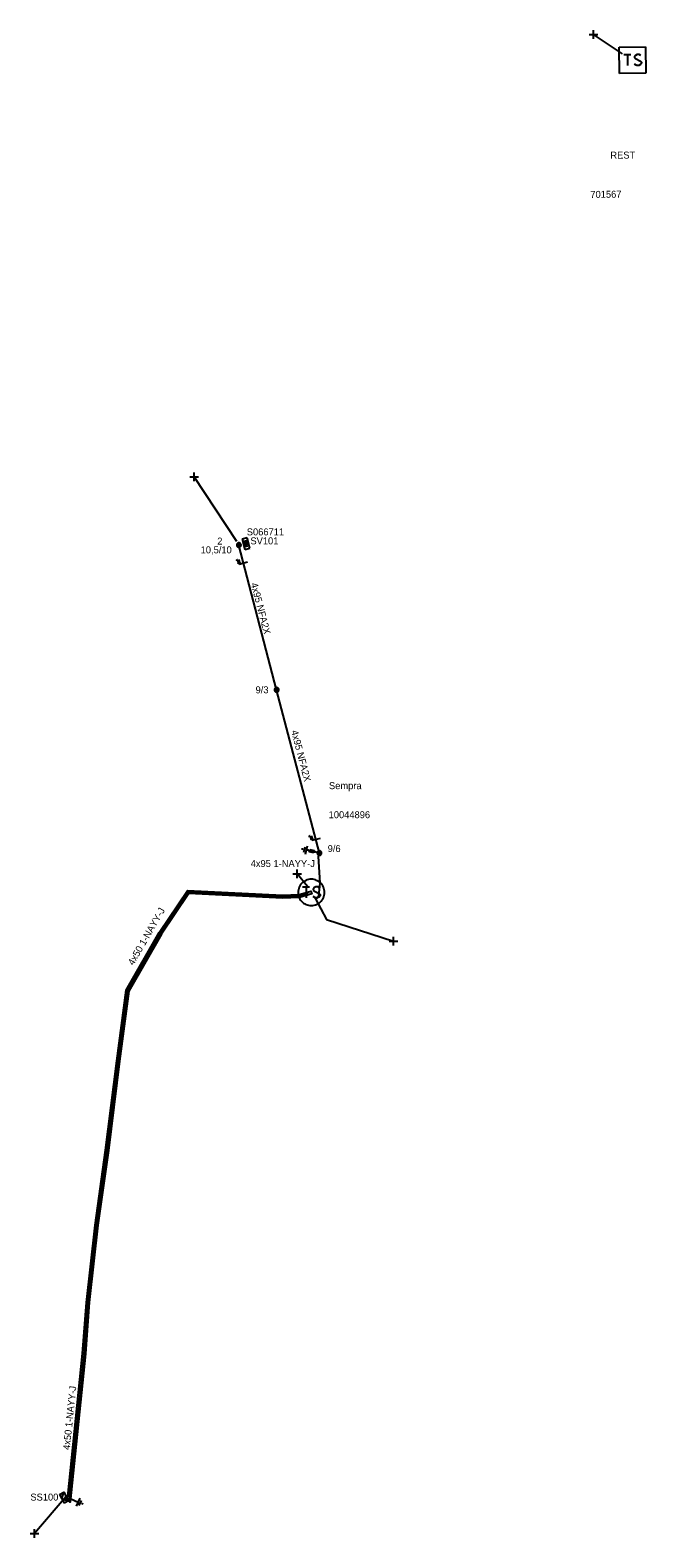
# Model space of a CAD drawing. Extents: x -748492 to -735633, y -1146251 to -1139940.
# Drawn here: x -736938.6 to -736850.2, y -1142511.7 to -1142295.3 of the extents above; entities that cross this region are included whole.
import ezdxf

# ---------------------------------------------------------------- set-up
doc = ezdxf.new("R2010")
doc.units = 0
for name, color, linetype in [('Vrstva 1', 7, 'Continuous'), ('Vrstva 12', 7, 'Continuous'), ('Vrstva 13', 7, 'Continuous'), ('Vrstva 14', 7, 'Continuous'), ('Vrstva 15', 7, 'Continuous'), ('Vrstva 16', 7, 'Continuous'), ('Vrstva 18', 7, 'Continuous'), ('Vrstva 2', 7, 'Continuous'), ('Vrstva 20', 7, 'Continuous'), ('Vrstva 25', 7, 'Continuous'), ('Vrstva 26', 7, 'Continuous'), ('Vrstva 27', 7, 'Continuous'), ('Vrstva 28', 7, 'Continuous'), ('Vrstva 29', 7, 'Continuous'), ('Vrstva 30', 7, 'Continuous'), ('Vrstva 31', 7, 'Continuous'), ('Vrstva 33', 7, 'Continuous'), ('Vrstva 34', 7, 'Continuous'), ('Vrstva 5', 7, 'Continuous'), ('Vrstva 50', 7, 'Continuous'), ('Vrstva 51', 7, 'Continuous'), ('Vrstva 59', 7, 'Continuous'), ('Vrstva 6', 7, 'Continuous'), ('Vrstva 8', 7, 'Continuous'), ('Vrstva 9', 7, 'Continuous')]:
    doc.layers.add(name, color=color, linetype=linetype)

# ---------------------------------------------------------------- blocks, each defined once
blk = doc.blocks.new('NN440')
at = {"layer": 'Vrstva 2'}
for points in [[(0.63, 0), (0.63, 0.06), (0.62, 0.13), (0.6, 0.19), (0.58, 0.25), (0.55, 0.31), (0.51, 0.37), (0.47, 0.42), (0.42, 0.46), (0.37, 0.51), (0.32, 0.54), (0.26, 0.57), (0.2, 0.59), (0.13, 0.61), (0.07, 0.62), (0, 0.63), (-0.06, 0.62), (-0.13, 0.61), (-0.19, 0.59), (-0.26, 0.57), (-0.31, 0.54), (-0.37, 0.51), (-0.42, 0.46), (-0.47, 0.42), (-0.51, 0.37), (-0.54, 0.31), (-0.57, 0.25), (-0.6, 0.19), (-0.62, 0.13), (-0.63, 0.06), (-0.63, 0), (-0.63, -0.07), (-0.62, -0.14), (-0.6, -0.2), (-0.57, -0.26), (-0.54, -0.32), (-0.51, -0.37), (-0.47, -0.43), (-0.42, -0.47), (-0.37, -0.51), (-0.31, -0.55), (-0.26, -0.58), (-0.19, -0.6), (-0.13, -0.62), (-0.06, -0.63), (0, -0.63), (0.07, -0.63), (0.13, -0.62), (0.2, -0.6), (0.26, -0.58), (0.32, -0.55), (0.37, -0.51), (0.42, -0.47), (0.47, -0.43), (0.51, -0.37), (0.55, -0.32), (0.58, -0.26), (0.6, -0.2), (0.62, -0.14), (0.63, -0.07), (0.63, 0)], [(-0.63, 0), (0.63, 0)], [(-0.6, -0.18), (0.57, -0.18)], [(-0.51, -0.32), (0.5, -0.32)], [(-0.37, -0.47), (0.35, -0.47)]]:
    blk.add_lwpolyline(points, dxfattribs=at)
blk = doc.blocks.new('NN840')
at = {"layer": 'Vrstva 15'}
for points in [[(0, 0.62), (0, -0.63)], [(-0.75, -0.71), (-0.75, -0.66)], [(-0.73, -0.76), (-0.75, -0.71)], [(-0.66, -0.8), (-0.73, -0.76)], [(-0.63, -0.8), (-0.66, -0.8)], [(-0.56, -0.76), (-0.63, -0.8)], [(-0.54, -0.71), (-0.56, -0.76)], [(-0.54, -0.38), (-0.54, -0.71)], [(-0.33, -0.38), (-0.33, -0.8)], [(-0.33, -0.64), (-0.13, -0.38)], [(-0.26, -0.56), (-0.09, -0.8)]]:
    blk.add_lwpolyline(points, dxfattribs=at)
blk = doc.blocks.new('NN800')
at = {"layer": 'Vrstva 1'}
for points in [[(-0.44, 0.44), (0.44, -0.44)], [(-0.44, -0.44), (0.44, 0.44)]]:
    blk.add_lwpolyline(points, dxfattribs=at)
blk = doc.blocks.new('NN820')
at = {"layer": 'Vrstva 13'}
for points in [[(0, 0), (0, -1.05)], [(-0.16, -0.81), (0.16, -0.81)], [(-0.16, -1.47), (-0.16, -0.81)], [(0.16, -1.47), (-0.16, -1.47)], [(0, -1.05), (-0.06, -0.93)], [(0, -1.05), (0.06, -0.93)], [(0, -1.47), (0, -1.87)], [(0.16, -0.81), (0.16, -1.47)]]:
    blk.add_lwpolyline(points, dxfattribs=at)
blk = doc.blocks.new('NN620')
at = {"layer": 'Vrstva 8'}
for points in [[(0.75, 0), (-0.75, 0)], [(-0.75, 0), (-0.75, -0.75)], [(0.75, -0.75), (0.75, 0)], [(-0.75, -0.75), (0.75, -0.75)], [(0.37, -0.18), (-0.38, -0.18)], [(-0.38, -0.18), (-0.38, -0.56)], [(-0.38, -0.56), (0.37, -0.56)], [(0.32, -0.23), (-0.33, -0.23)], [(-0.33, -0.23), (-0.33, -0.51)], [(-0.33, -0.51), (0.32, -0.51)], [(0.27, -0.27), (-0.28, -0.27)], [(-0.28, -0.27), (-0.28, -0.46)], [(-0.28, -0.46), (0.27, -0.46)], [(0.23, -0.32), (-0.23, -0.32)], [(-0.23, -0.32), (-0.23, -0.42)], [(-0.23, -0.42), (0.23, -0.42)], [(-0.19, -0.37), (0.19, -0.37)], [(0.23, -0.42), (0.23, -0.32)], [(0.27, -0.46), (0.27, -0.27)], [(0.32, -0.51), (0.32, -0.23)], [(0.37, -0.56), (0.37, -0.18)]]:
    blk.add_lwpolyline(points, dxfattribs=at)
blk = doc.blocks.new('NN630')
at = {"layer": 'Vrstva 9'}
for points in [[(0, -0.7), (-0.7, 0)], [(-0.7, -0.7), (-0.7, 0), (0.7, 0), (0.7, -0.7)], [(-0.7, -0.7), (0.7, -0.7)], [(0, -0.7), (0.7, 0)]]:
    blk.add_lwpolyline(points, dxfattribs=at)
blk = doc.blocks.new('NN810')
at = {"layer": 'Vrstva 14'}
for points in [[(0.63, -1.89), (-0.62, -1.89)], [(0, -0.64), (0, -1.89)], [(0.39, -2.2), (-0.4, -2.2)], [(0, -2.52), (-0.12, -2.52)], [(0.14, -2.52), (0, -2.52)]]:
    blk.add_lwpolyline(points, dxfattribs=at)
blk = doc.blocks.new('NN640')
at = {"layer": 'Vrstva 6'}
for points in [[(-1.89, 1.89), (1.89, 1.89)], [(-1.89, -1.89), (-1.89, 1.89)], [(-1.26, 0.79), (-0.22, 0.79)], [(-0.73, 0.79), (-0.73, -0.79)], [(1.2, 0.66), (0.94, 0.79), (0.66, 0.79), (0.41, 0.66), (0.28, 0.47), (0.28, 0.41), (0.41, 0.22), (1.13, -0.16), (1.26, -0.32), (1.26, -0.47), (1.13, -0.66), (0.91, -0.79), (0.63, -0.79), (0.5, -0.73), (0.28, -0.6)], [(1.89, 1.89), (1.89, -1.89)], [(1.89, -1.89), (-1.89, -1.89)]]:
    blk.add_lwpolyline(points, dxfattribs=at)
blk = doc.blocks.new('NN610')
at = {"layer": 'Vrstva 6'}
for points in [[(1.88, 0), (1.87, 0.2), (1.84, 0.39), (1.79, 0.58), (1.72, 0.77), (1.63, 0.94), (1.52, 1.11), (1.4, 1.26), (1.26, 1.4), (1.1, 1.53), (0.94, 1.63), (0.76, 1.72), (0.58, 1.8), (0.19, 1.88), (0.19, 1.88), (-0.01, 1.89), (-0.21, 1.88), (-0.4, 1.85), (-0.59, 1.8), (-0.78, 1.72), (-0.95, 1.63), (-1.12, 1.53), (-1.27, 1.4), (-1.41, 1.26), (-1.54, 1.11), (-1.64, 0.94), (-1.73, 0.77), (-1.8, 0.58), (-1.86, 0.39), (-1.89, 0.2), (-1.9, 0), (-1.89, -0.2), (-1.86, -0.39), (-1.8, -0.58), (-1.73, -0.77), (-1.64, -0.95), (-1.54, -1.11), (-1.41, -1.27), (-1.27, -1.41), (-1.12, -1.53), (-0.95, -1.64), (-0.78, -1.73), (-0.59, -1.8), (-0.4, -1.85), (-0.21, -1.88), (-0.01, -1.89), (0.19, -1.88), (0.39, -1.85), (0.58, -1.8), (0.76, -1.73), (0.94, -1.64), (1.1, -1.53), (1.26, -1.41), (1.4, -1.27), (1.52, -1.11), (1.63, -0.95), (1.72, -0.77), (1.79, -0.58), (1.84, -0.39), (1.87, -0.2), (1.88, 0)], [(-1.27, 0.78), (-0.26, 0.78)], [(-0.76, 0.78), (-0.76, -0.79)], [(1.19, 0.66), (0.94, 0.78), (0.62, 0.78), (0.37, 0.66), (0.24, 0.47), (0.24, 0.4), (0.37, 0.22), (1.12, -0.16), (1.25, -0.32), (1.25, -0.48), (1.12, -0.67), (0.87, -0.79), (0.62, -0.79), (0.49, -0.73), (0.24, -0.6)]]:
    blk.add_lwpolyline(points, dxfattribs=at)

msp = doc.modelspace()

# ---------------------------------------------------------------- linework, layer by layer
at = {"layer": 'Vrstva 20'}
msp.add_lwpolyline([(-736933.25, -1142505.66), (-736933.12, -1142505.79), (-736931.02, -1142485.28), (-736930.47, -1142477.93), (-736929.22, -1142466.83), (-736927.73, -1142456.08), (-736926.11, -1142443.26), (-736924.78, -1142433.11), (-736920.05, -1142424.84), (-736915.98, -1142418.82), (-736902.33, -1142419.5), (-736899.95, -1142419.39), (-736898.25, -1142418.89), (-736898.13, -1142419.27), (-736899.89, -1142419.79), (-736902.33, -1142419.9), (-736915.78, -1142419.24), (-736919.71, -1142425.06), (-736924.4, -1142433.25), (-736925.71, -1142443.32), (-736927.33, -1142456.14), (-736928.82, -1142466.87), (-736930.07, -1142477.97), (-736930.62, -1142485.32), (-736932.8, -1142506.59), (-736932.85, -1142506.61), (-736933.53, -1142505.94)], close=True, dxfattribs=at)
at = {"layer": 'Vrstva 5'}
for points in [[(-736897.81, -1142419.79), (-736897.42, -1142419.93), (-736897.11, -1142419.55), (-736896.91, -1142417.74), (-736897.02, -1142416.18), (-736897.15, -1142413.93), (-736897.03, -1142413.43)], [(-736898.65, -1142419.22), (-736899.92, -1142419.59), (-736902.33, -1142419.7), (-736915.88, -1142419.03), (-736919.88, -1142424.95), (-736924.59, -1142433.18), (-736925.91, -1142443.29), (-736927.53, -1142456.11), (-736929.02, -1142466.85), (-736930.27, -1142477.95), (-736930.82, -1142485.3), (-736932.96, -1142506.22), (-736933.39, -1142505.8)]]:
    msp.add_lwpolyline(points, dxfattribs=at)
at = {"layer": 'Vrstva 50'}
msp.add_lwpolyline([(-736897.03, -1142413.43), (-736903.17, -1142390), (-736908.59, -1142369.22)], dxfattribs=at)
at = {"layer": 'Vrstva 59'}
for points in [[(-736853.54, -1142298.69), (-736857.69, -1142295.93)], [(-736908.91, -1142368.73), (-736915, -1142359.45)], [(-736898.75, -1142418.25), (-736900.21, -1142416.41)], [(-736897.63, -1142419.91), (-736896, -1142422.99), (-736886.4, -1142426.1)], [(-736933.39, -1142505.8), (-736937.93, -1142511.11)]]:
    msp.add_lwpolyline(points, dxfattribs=at)

# ---------------------------------------------------------------- block references
at = {"layer": 'Vrstva 13', "xscale": 0.5}
for p, yscale, rotation in [((-736908.59, -1142369.22), 0.5000000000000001, -76.40978892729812), ((-736903.17, -1142390), 0.5, -80.43170555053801), ((-736897.03, -1142413.43), 0.49999999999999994, -75.18203163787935)]:
    msp.add_blockref('NN440', p, dxfattribs=dict(at, yscale=yscale, rotation=rotation))
at = {"layer": 'Vrstva 15'}
for p, rotation in [((-736897.03, -1142413.43), -103.49573330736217), ((-736933.41, -1142505.83), 65.98977775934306)]:
    msp.add_blockref('NN810', p, dxfattribs=dict(at, rotation=rotation))
at = {"layer": 'Vrstva 16', "rotation": -103.49573330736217}
msp.add_blockref('NN820', (-736897.03, -1142413.43), dxfattribs=at)
at = {"layer": 'Vrstva 18'}
for p, rotation in [((-736907.96, -1142371.84), -75.38699448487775), ((-736897.53, -1142411.48), -75.40700278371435)]:
    msp.add_blockref('NN840', p, dxfattribs=dict(at, rotation=rotation))
at = {"layer": 'Vrstva 25', "rotation": 0.5058555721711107}
msp.add_blockref('NN640', (-736852.09, -1142299.6), dxfattribs=at)
at = {"layer": 'Vrstva 25'}
msp.add_blockref('NN610', (-736898.19, -1142419.08), dxfattribs=at)
at = {"layer": 'Vrstva 28', "rotation": 104.61281404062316}
msp.add_blockref('NN620', (-736907.94, -1142369.12), dxfattribs=at)
at = {"layer": 'Vrstva 31', "rotation": -62.414907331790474}
msp.add_blockref('NN630', (-736933.39, -1142505.8), dxfattribs=at)
at = {"layer": 'Vrstva 34'}
for p, rotation in [((-736857.69, -1142295.93), 45), ((-736915, -1142359.45), 44.99999995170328), ((-736900.21, -1142416.41), 45), ((-736886.4, -1142426.1), 45), ((-736937.93, -1142511.11), 45)]:
    msp.add_blockref('NN800', p, dxfattribs=dict(at, rotation=rotation))

# ---------------------------------------------------------------- texts
at = {"layer": 'Vrstva 12'}
for s, p in [('10,5/10', (-736914.08, -1142370.41)), ('9/3', (-736906.2, -1142390.5)), ('9/6', (-736895.85, -1142413.29))]:
    msp.add_text(s, height=1, dxfattribs=at).set_placement(p)
at = {"layer": 'Vrstva 14'}
msp.add_text('2', height=1, dxfattribs=at).set_placement((-736911.7, -1142369.15))
at = {"layer": 'Vrstva 26'}
msp.add_text('701567', height=1, rotation=0.506, dxfattribs=at).set_placement((-736858.14, -1142319.39))
msp.add_text('10044896', height=1, dxfattribs=at).set_placement((-736895.71, -1142408.43))
at = {"layer": 'Vrstva 27'}
msp.add_text('REST', height=1, rotation=0.506, dxfattribs=at).set_placement((-736855.27, -1142313.76))
msp.add_text('Sempra', height=1, dxfattribs=at).set_placement((-736895.66, -1142404.26))
at = {"layer": 'Vrstva 29'}
msp.add_text('S066711', height=1, dxfattribs=at).set_placement((-736907.46, -1142367.83))
at = {"layer": 'Vrstva 30'}
msp.add_text('SV101', height=1, dxfattribs=at).set_placement((-736906.94, -1142369.12))
at = {"layer": 'Vrstva 33'}
msp.add_text('SS100', height=1, dxfattribs=at).set_placement((-736938.52, -1142506.38))
at = {"layer": 'Vrstva 51'}
for rotation, p in [(284.613, (-736906.9, -1142374.77)), (284.593, (-736901.11, -1142395.93))]:
    msp.add_text('4x95 NFA2X', height=1, rotation=rotation, dxfattribs=at).set_placement(p)
at = {"layer": 'Vrstva 6'}
msp.add_text('4x95 1-NAYY-J', height=1, dxfattribs=at).set_placement((-736906.9, -1142415.44))
for rotation, p in [(60.218, (-736923.73, -1142429.64)), (84.159, (-736932.86, -1142499.15))]:
    msp.add_text('4x50 1-NAYY-J', height=1, rotation=rotation, dxfattribs=at).set_placement(p)

doc.saveas('drawing.dxf')
